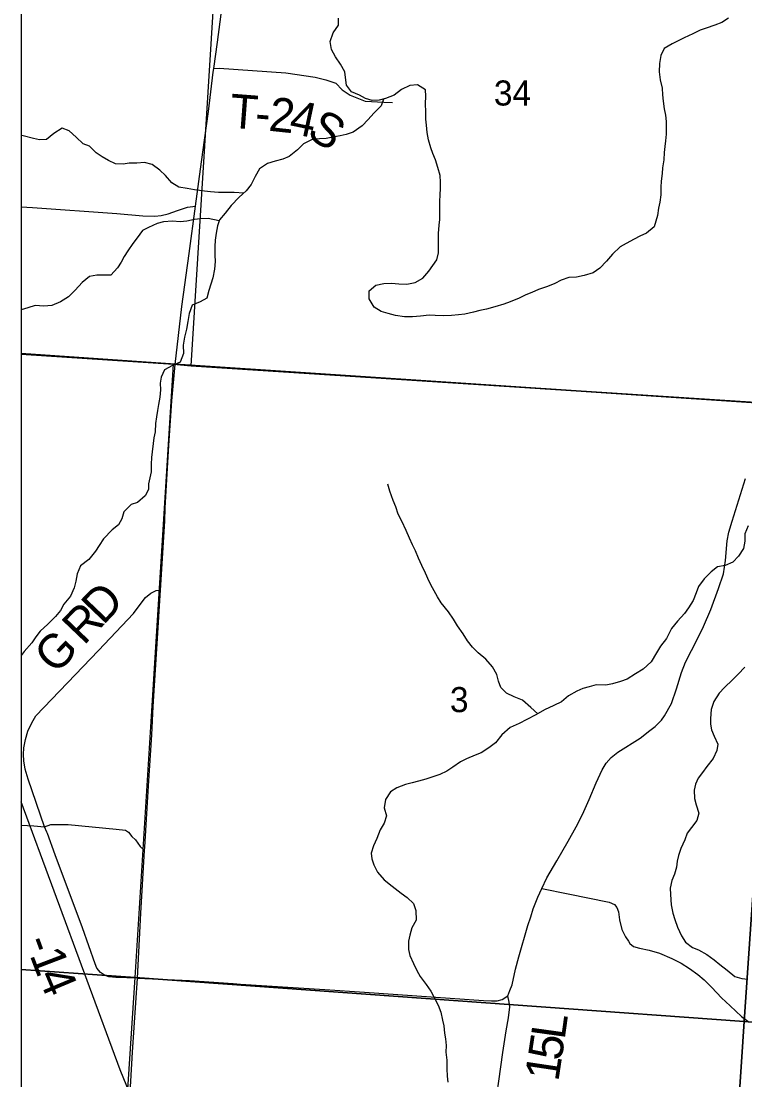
# Model space of a CAD drawing. Extents: x 0 to 34, y 0 to 22.
# Drawn here: x 2.1 to 3.309, y 17.985 to 19.753 of the extents above; entities that cross this region are included whole.
import ezdxf

# ---------------------------------------------------------------- set-up
doc = ezdxf.new("R2010")
doc.units = 0
for name, color, linetype in [('Default', 7, 'Continuous'), ('GM_X_County_Road', 7, 'Continuous'), ('GM_X_County_Road_Text', 7, 'Continuous'), ('GM_X_Minor_River', 7, 'Continuous'), ('GM_X_Rail_Line', 7, 'Continuous'), ('GM_X_Section', 7, 'Continuous'), ('GM_X_Section_Text', 7, 'Continuous'), ('GM_X_State_Route', 7, 'Continuous'), ('GM_X_Township_Road', 7, 'Continuous'), ('GM_X_Township_Road_Text', 7, 'Continuous'), ('SC_Scratch1', 7, 'Continuous'), ('SH_Data', 7, 'Continuous')]:
    doc.layers.add(name, color=color, linetype=linetype)

msp = doc.modelspace()

# ---------------------------------------------------------------- linework, layer by layer
at = {"layer": 'Default'}
for points in [[(2.1, 20.207), (2.1, 19.197), (2.3543, 19.1806), (2.3838, 19.1776), (2.446, 20.1823)], [(2.1, 19.197), (2.1, 18.1694), (2.2906, 18.1558), (2.3543, 19.1806)], [(2.1, 18.1694), (2.1, 17.1522), (2.2239, 17.1453), (2.2906, 18.1558)]]:
    msp.add_lwpolyline(points, close=True, dxfattribs=at)
at = {"layer": 'GM_X_County_Road'}
for points in [[(2.1431, 18.3985), (2.139, 18.4078), (2.1117, 18.4871), (2.1064, 18.504), (2.1043, 18.5178), (2.1037, 18.5286), (2.1043, 18.5396), (2.107, 18.5536), (2.1112, 18.5675), (2.1176, 18.5816), (2.1246, 18.5933), (2.1774, 18.6483), (2.2291, 18.702), (2.2874, 18.7638), (2.2969, 18.777), (2.3079, 18.791), (2.3166, 18.798), (2.3253, 18.8024), (2.3329, 18.8027)], [(2.2941, 18.1548), (2.2581, 18.1557), (2.2463, 18.1572), (2.2389, 18.1599), (2.2325, 18.1641), (2.2266, 18.1714), (2.2238, 18.1786), (2.2022, 18.2392), (2.1568, 18.361), (2.1439, 18.3966), (2.1431, 18.3985)]]:
    msp.add_lwpolyline(points, dxfattribs=at)
at = {"layer": 'GM_X_Minor_River'}
for points in [[(2.7752, 19.6154), (2.7756, 19.6283), (2.7752, 19.6385), (2.7619, 19.6472), (2.749, 19.646), (2.7354, 19.6395), (2.723, 19.63), (2.7086, 19.6243), (2.698, 19.6216), (2.6859, 19.6208), (2.6753, 19.6242), (2.665, 19.6299), (2.6518, 19.6352), (2.6434, 19.6465), (2.6415, 19.6594), (2.6407, 19.6689), (2.6335, 19.6818), (2.6247, 19.6939), (2.6182, 19.706), (2.6159, 19.7196), (2.6212, 19.7337), (2.6302, 19.7466), (2.6302, 19.7587)], [(3.2813, 19.7584), (3.2703, 19.7512), (3.2582, 19.747), (3.2439, 19.742), (3.234, 19.7382), (3.2215, 19.7325), (3.2072, 19.7256)], [(3.2072, 19.7256), (3.1974, 19.7203), (3.1872, 19.7157), (3.1739, 19.7077), (3.1683, 19.6959), (3.1661, 19.6827), (3.1654, 19.6686), (3.1673, 19.6554), (3.1704, 19.6417), (3.1711, 19.6304), (3.1723, 19.6198), (3.1739, 19.6069), (3.1758, 19.5963), (3.177, 19.586), (3.1774, 19.5762), (3.1774, 19.5648), (3.1763, 19.5538), (3.1748, 19.5439), (3.1737, 19.5341), (3.173, 19.5216), (3.1708, 19.5087), (3.1704, 19.4988), (3.169, 19.4863), (3.1682, 19.4761), (3.1683, 19.4632), (3.1668, 19.451), (3.1646, 19.4412), (3.1627, 19.4287), (3.1601, 19.4192), (3.1571, 19.4097), (3.1443, 19.3994), (3.1333, 19.3941), (3.1235, 19.3895), (3.1102, 19.3823), (3.1004, 19.3762), (3.0876, 19.3644), (3.0774, 19.3526), (3.0661, 19.3409), (3.0551, 19.3332), (3.04, 19.3287), (3.0272, 19.326), (3.0147, 19.3252), (3.0018, 19.3206), (2.9912, 19.3153), (2.9791, 19.3103), (2.964, 19.3054), (2.9527, 19.3004), (2.9428, 19.2962), (2.9315, 19.2909), (2.9164, 19.2848), (2.9058, 19.2809), (2.891, 19.2764), (2.877, 19.2722), (2.8657, 19.2699), (2.8555, 19.2676), (2.8411, 19.2641), (2.8305, 19.2629), (2.8184, 19.2618), (2.8055, 19.2614), (2.7915, 19.2617), (2.7813, 19.2624), (2.7669, 19.2609), (2.7533, 19.2597), (2.7404, 19.2597), (2.7249, 19.2616), (2.7128, 19.2649), (2.701, 19.2683), (2.6893, 19.2759), (2.6813, 19.2895), (2.6812, 19.3028), (2.6922, 19.3127), (2.7054, 19.315), (2.7187, 19.3157), (2.7308, 19.3146), (2.744, 19.3143), (2.7577, 19.317), (2.7705, 19.3242), (2.7807, 19.3356), (2.7875, 19.3455), (2.7939, 19.355), (2.7969, 19.3667), (2.7972, 19.3766), (2.7971, 19.3986), (2.7979, 19.4126), (2.799, 19.4221), (2.7993, 19.4411), (2.7992, 19.4528), (2.7996, 19.4627), (2.8003, 19.4744), (2.8003, 19.4847), (2.7995, 19.4956), (2.796, 19.5089), (2.7922, 19.5218), (2.7876, 19.5324), (2.7842, 19.5419), (2.7804, 19.5551), (2.778, 19.5672), (2.7769, 19.5797), (2.7757, 19.59), (2.7757, 19.6021), (2.7752, 19.6154)], [(2.7049, 19.6234), (2.7011, 19.6118), (2.689, 19.5996), (2.6796, 19.589), (2.6694, 19.5787), (2.6546, 19.5681), (2.6425, 19.5639), (2.6327, 19.562), (2.6202, 19.5597), (2.6096, 19.5577), (2.5983, 19.5566), (2.585, 19.5554), (2.5714, 19.5485), (2.5612, 19.5383), (2.5476, 19.5273), (2.5371, 19.5227), (2.5242, 19.5196), (2.5113, 19.5158), (2.4981, 19.507), (2.4906, 19.4941), (2.4842, 19.4808), (2.4755, 19.4698), (2.4638, 19.4592), (2.4506, 19.4455), (2.4408, 19.4326), (2.431, 19.4216), (2.428, 19.4113), (2.4258, 19.3992), (2.4239, 19.3878), (2.4236, 19.3772), (2.4236, 19.3624), (2.4237, 19.3522), (2.423, 19.3393), (2.42, 19.3249), (2.417, 19.3139), (2.4136, 19.3033), (2.4099, 19.2907), (2.3989, 19.2846), (2.3853, 19.2789), (2.3804, 19.2649), (2.3782, 19.2516), (2.376, 19.2391), (2.3726, 19.2254), (2.3707, 19.2122), (2.3712, 19.1985), (2.3655, 19.1841), (2.3527, 19.178), (2.3395, 19.1711), (2.3338, 19.159), (2.3323, 19.1488), (2.3324, 19.1374), (2.3317, 19.1256), (2.3294, 19.1131), (2.3276, 19.1033), (2.3261, 19.0926), (2.3246, 19.0813), (2.3235, 19.0676), (2.3217, 19.0574), (2.3202, 19.0479), (2.3187, 19.0342), (2.3176, 19.0248), (2.3173, 19.0134), (2.3169, 19.0005), (2.3147, 18.9906), (2.3128, 18.9804), (2.3129, 18.9709), (2.3072, 18.9603), (2.294, 18.9493), (2.2838, 18.9462), (2.2713, 18.9337), (2.2683, 18.9223), (2.2623, 18.912), (2.2517, 18.904), (2.2374, 18.8888), (2.2303, 18.8774), (2.2242, 18.8679), (2.2129, 18.8543), (2.1993, 18.8436), (2.1937, 18.8303), (2.1911, 18.8178), (2.1885, 18.8068), (2.1821, 18.7932), (2.1715, 18.7795), (2.1655, 18.7688), (2.1572, 18.759), (2.1447, 18.746), (2.1315, 18.7346), (2.1244, 18.7248), (2.118, 18.7149), (2.1048, 18.7008), (2.1, 18.6936)], [(2.4716, 19.4663), (2.4555, 19.4675), (2.4437, 19.4671), (2.4297, 19.4674), (2.4161, 19.4685), (2.4063, 19.4693), (2.3892, 19.4719), (2.3771, 19.4738), (2.3635, 19.476), (2.3517, 19.4836), (2.3411, 19.4957), (2.3316, 19.5047), (2.3187, 19.5142), (2.3062, 19.5172), (2.2929, 19.5164), (2.2804, 19.516), (2.2706, 19.5148), (2.2577, 19.5152), (2.246, 19.5208), (2.2354, 19.5269), (2.2251, 19.5337), (2.2141, 19.5446), (2.2035, 19.5488), (2.1921, 19.5597), (2.1803, 19.5703), (2.1682, 19.5745), (2.1546, 19.5657), (2.1421, 19.5558), (2.1304, 19.5554), (2.1206, 19.5573), (2.1031, 19.5618), (2.1, 19.5624)], [(2.4306, 19.42), (2.4125, 19.4238), (2.3992, 19.4234), (2.3894, 19.4219), (2.3765, 19.4192), (2.3655, 19.4184), (2.3527, 19.4191), (2.3375, 19.4183), (2.3269, 19.4153), (2.3126, 19.4088), (2.3028, 19.4038), (2.2937, 19.3917), (2.2865, 19.3822), (2.2779, 19.37), (2.2719, 19.3602), (2.267, 19.3507), (2.2609, 19.3412), (2.2496, 19.3294), (2.2261, 19.3293), (2.214, 19.3267), (2.2016, 19.3168), (2.1903, 19.3039), (2.1789, 19.2932), (2.1657, 19.2848), (2.151, 19.2787), (2.1381, 19.2772), (2.1233, 19.2783), (2.1112, 19.2745), (2.1, 19.2713)], [(2.9626, 18.5966), (2.9511, 18.607), (2.9371, 18.6194), (2.9234, 18.6247), (2.9105, 18.6311), (2.901, 18.6402), (2.8972, 18.6508), (2.8945, 18.6622), (2.8869, 18.6747), (2.8759, 18.6875), (2.8634, 18.6985), (2.8535, 18.708), (2.8455, 18.7182), (2.8383, 18.7303), (2.8288, 18.7435), (2.8219, 18.7545), (2.8136, 18.7666), (2.8014, 18.7818), (2.7953, 18.792), (2.7869, 18.8068), (2.7816, 18.8177), (2.7751, 18.8314), (2.769, 18.8439), (2.7633, 18.8564), (2.7583, 18.8685), (2.7534, 18.8787), (2.7484, 18.8901), (2.7431, 18.9026), (2.7359, 18.9181), (2.7298, 18.9302), (2.7256, 18.9423), (2.7214, 18.9526), (2.7156, 18.9681), (2.7122, 18.9802)], [(3.3139, 18.9104), (3.3083, 18.8971), (3.3083, 18.885), (3.3061, 18.8725), (3.2978, 18.8596), (3.2884, 18.8497), (3.2755, 18.8443), (3.263, 18.842), (3.2521, 18.8337), (3.2404, 18.8219), (3.231, 18.8093), (3.2272, 18.7983), (3.222, 18.7858), (3.2144, 18.7737), (3.208, 18.7638), (3.1959, 18.7512), (3.1861, 18.7391), (3.1775, 18.7224), (3.1677, 18.7095), (3.1609, 18.6981), (3.1523, 18.6833), (3.1387, 18.6711), (3.1262, 18.6631), (3.1122, 18.6544), (3.1009, 18.6505), (3.0873, 18.6467), (3.0763, 18.6444), (3.06, 18.6448), (3.0483, 18.6417), (3.0381, 18.6386), (3.0279, 18.6344), (3.0139, 18.6264), (3.0026, 18.6166), (2.9893, 18.6101), (2.9742, 18.6032), (2.9595, 18.5948), (2.9447, 18.5868), (2.9315, 18.58), (2.9164, 18.5735), (2.9028, 18.5613), (2.8919, 18.5477), (2.8809, 18.5397), (2.8681, 18.5313), (2.8582, 18.5271), (2.8435, 18.5214), (2.8337, 18.5164), (2.8208, 18.5073), (2.8106, 18.5005), (2.7989, 18.4951), (2.7876, 18.4909), (2.7759, 18.4871), (2.7638, 18.484), (2.7528, 18.4814), (2.7418, 18.4783)], [(3.3086, 18.6742), (3.2973, 18.6628), (3.2882, 18.6533), (3.2743, 18.6403), (3.2656, 18.6308), (3.2566, 18.6172), (3.2524, 18.6039), (3.251, 18.5887), (3.251, 18.5789), (3.2526, 18.5694), (3.2571, 18.5592), (3.2632, 18.5459), (3.2618, 18.5349), (3.2557, 18.522), (3.2452, 18.5087), (3.2376, 18.4985), (3.2305, 18.489), (3.226, 18.4787), (3.2237, 18.4688), (3.2245, 18.4552), (3.2272, 18.4442), (3.2318, 18.4302), (3.2281, 18.418), (3.2194, 18.4067), (3.2122, 18.3968), (3.2085, 18.3862), (3.2017, 18.3713), (3.1976, 18.36), (3.1957, 18.3501), (3.1946, 18.3402), (3.1909, 18.3285), (3.1864, 18.3178), (3.1838, 18.3053), (3.1842, 18.2947), (3.1854, 18.2773), (3.1884, 18.2633), (3.1915, 18.253), (3.1961, 18.2398), (3.2026, 18.2258), (3.2094, 18.2148), (3.2212, 18.2061), (3.2314, 18.2023), (3.2451, 18.1944), (3.2572, 18.1853), (3.2667, 18.1778), (3.2792, 18.1683), (3.2917, 18.1577), (3.3035, 18.1543), (3.3137, 18.1532)], [(2.7418, 18.4783), (2.7271, 18.4726), (2.7169, 18.4661), (2.7086, 18.4532), (2.7064, 18.4392), (2.7102, 18.4263), (2.7064, 18.4138), (2.6997, 18.4024), (2.6937, 18.3883), (2.6884, 18.3758), (2.6846, 18.3637), (2.6854, 18.3542), (2.6889, 18.3443), (2.6953, 18.3322), (2.7064, 18.319), (2.7197, 18.3084), (2.7345, 18.297), (2.7447, 18.2895), (2.7553, 18.2796), (2.7592, 18.2679), (2.7596, 18.252), (2.7524, 18.2387), (2.7491, 18.2265), (2.7468, 18.2167), (2.7469, 18.2027), (2.7492, 18.1928), (2.7553, 18.1792), (2.7606, 18.1678), (2.7663, 18.1576), (2.7762, 18.1443), (2.7842, 18.1334), (2.7895, 18.1227), (2.7964, 18.1095), (2.8006, 18.0978), (2.8037, 18.0849), (2.8056, 18.075), (2.8068, 18.0629), (2.8087, 18.0534), (2.8095, 18.0424), (2.8091, 18.0314), (2.8107, 18.0178), (2.8111, 18.0034), (2.8115, 17.9912), (2.8127, 17.9814)]]:
    msp.add_lwpolyline(points, dxfattribs=at)
at = {"layer": 'GM_X_Rail_Line'}
msp.add_lwpolyline([(2.1, 16.9893), (2.1704, 17.1051), (2.2013, 17.1731), (2.2243, 17.2382), (2.2428, 17.3133), (2.3248, 17.6437), (2.3306, 17.7087), (2.3319, 17.774), (2.3234, 17.8446), (2.3066, 17.9007), (2.2655, 18.002), (2.1, 18.4495)], dxfattribs=at)
at = {"layer": 'GM_X_Section'}
for points in [[(3.4572, 20.1141), (3.4007, 19.112), (3.378, 19.1131), (2.3838, 19.1776), (2.446, 20.1823)], [(2.3543, 19.1806), (2.3838, 19.1776), (3.378, 19.1131), (3.3075, 18.0826), (2.2906, 18.1558)], [(3.378, 19.1131), (3.4007, 19.112), (4.3808, 19.0475), (4.3187, 18.0057), (3.3075, 18.0826)], [(2.2906, 18.1558), (3.3075, 18.0826), (3.2396, 17.0555), (2.2239, 17.1453)], [(4.3187, 18.0057), (4.2561, 17.0047), (3.2396, 17.0555), (3.3075, 18.0826)]]:
    msp.add_lwpolyline(points, close=True, dxfattribs=at)
at = {"layer": 'GM_X_State_Route'}
for points in [[(2.3912, 19.4446), (2.3997, 19.506), (2.4063, 19.5548), (2.4127, 19.6028), (2.4207, 19.6683), (2.4216, 19.6746), (2.4278, 19.7185), (2.4366, 19.7864), (2.4499, 19.8758), (2.465, 19.9651), (2.5191, 20.2008), (2.5499, 20.3338), (2.5565, 20.3632)], [(2.2941, 18.1548), (2.3, 18.2633), (2.3062, 18.3682), (2.3066, 18.3739), (2.3128, 18.4761), (2.3181, 18.5614), (2.3206, 18.6084), (2.3281, 18.7311), (2.3301, 18.7586), (2.3329, 18.8027), (2.3397, 18.9183), (2.3406, 18.9404), (2.3468, 19.0449), (2.3516, 19.119), (2.3574, 19.1799), (2.3685, 19.2767), (2.3808, 19.3652), (2.3912, 19.4446)], [(2.454, 18.1459), (2.466, 18.1451), (2.6069, 18.1357), (2.6735, 18.1313), (2.872, 18.1173), (2.8854, 18.1169), (2.8949, 18.1169), (2.9032, 18.1194), (2.9125, 18.1254), (2.9163, 18.1343), (2.9199, 18.1438), (2.9258, 18.17), (2.9311, 18.1903), (2.9462, 18.2429), (2.9509, 18.2573), (2.9549, 18.2704), (2.9627, 18.2903), (2.9697, 18.3048), (2.978, 18.3222), (2.9948, 18.351), (3.0136, 18.3835), (3.0271, 18.4077), (3.0372, 18.4281), (3.0486, 18.4531), (3.0602, 18.4813), (3.0702, 18.5027), (3.0768, 18.5138), (3.0853, 18.5237), (3.0963, 18.5321), (3.1335, 18.5557), (3.1501, 18.5687), (3.159, 18.5754), (3.1692, 18.5858), (3.1744, 18.5932), (3.1858, 18.6135), (3.1946, 18.6382), (3.2028, 18.6652), (3.2097, 18.6825), (3.2292, 18.7218), (3.2396, 18.7421), (3.2519, 18.7708), (3.2647, 18.8059), (3.2727, 18.83), (3.2763, 18.8523), (3.2791, 18.8853), (3.282, 18.8999), (3.2872, 18.9182), (3.3095, 18.9897)], [(2.168, 17.1208), (2.176, 17.1355), (2.1997, 17.1916), (2.2065, 17.2125), (2.217, 17.2467), (2.2264, 17.2823), (2.2362, 17.3366), (2.2477, 17.4176), (2.2517, 17.4591), (2.2555, 17.5254), (2.2633, 17.6513), (2.2706, 17.7708), (2.2779, 17.8962), (2.2804, 17.9343), (2.2859, 18.031), (2.2941, 18.1548)], [(2.2941, 18.1548), (2.3813, 18.151), (2.454, 18.1459)]]:
    msp.add_lwpolyline(points, dxfattribs=at)
at = {"layer": 'GM_X_Township_Road'}
for points in [[(2.4216, 19.6746), (2.4308, 19.6749), (2.5419, 19.6673), (2.5911, 19.6601), (2.6087, 19.6555), (2.6253, 19.6497), (2.636, 19.6388), (2.6493, 19.63), (2.6747, 19.6197), (2.7058, 19.6184), (2.7203, 19.6175)], [(2.1, 19.4434), (2.1189, 19.4422), (2.2595, 19.4324), (2.3033, 19.4281), (2.3232, 19.4278), (2.3338, 19.429), (2.3453, 19.4317), (2.361, 19.4374), (2.3778, 19.443), (2.3912, 19.4446)], [(2.1, 18.4106), (2.121, 18.4091), (2.139, 18.4078)], [(2.139, 18.4078), (2.1494, 18.4116), (2.1783, 18.4114), (2.2588, 18.4036), (2.2742, 18.4023), (2.2793, 18.3985), (2.285, 18.3917), (2.291, 18.3862), (2.2988, 18.375), (2.3062, 18.3682)], [(2.9697, 18.3048), (3.0134, 18.2956), (3.0818, 18.2819), (3.091, 18.2778), (3.0948, 18.2731), (3.0974, 18.2658), (3.0991, 18.2522), (3.1029, 18.2364), (3.1095, 18.2241), (3.1141, 18.2167)], [(3.1141, 18.2167), (3.1164, 18.213), (3.1226, 18.208), (3.1325, 18.2051), (3.1489, 18.2018), (3.1661, 18.1964), (3.1865, 18.1878), (3.2022, 18.1798), (3.2163, 18.1712), (3.2298, 18.1611), (3.2408, 18.1518), (3.2535, 18.1392), (3.2694, 18.1219), (3.2839, 18.1089), (3.303, 18.0907), (3.3159, 18.0812)], [(2.8886, 17.9063), (2.8922, 17.9448), (2.8977, 17.9828), (2.9042, 18.0306), (2.9097, 18.0671), (2.9136, 18.0887), (2.9161, 18.1067), (2.915, 18.115), (2.9125, 18.1254)]]:
    msp.add_lwpolyline(points, dxfattribs=at)
at = {"layer": 'SC_Scratch1'}
for points in [[(5.53, 20.9), (2.1, 20.9), (2.1, 19.1982), (2.3572, 19.1804), (3.3448, 19.1146), (4.3628, 19.0495), (4.7394, 19.0241), (4.7997, 19.0196), (5.182, 18.9932), (5.4007, 18.9779), (5.4089, 19.0989), (5.4469, 19.6641), (5.4955, 20.3864)], [(2.1, 19.1982), (2.1, 14.1), (5.0535, 14.1), (5.0814, 14.5016), (5.1049, 14.8414), (5.1794, 15.9156), (5.2761, 17.2534), (5.2869, 17.4026), (5.3506, 18.2846), (5.3662, 18.4999), (5.4007, 18.9779), (5.182, 18.9932), (4.7997, 19.0196), (4.7394, 19.0241), (4.3628, 19.0495), (3.3448, 19.1146), (2.3572, 19.1804)]]:
    msp.add_lwpolyline(points, close=True, dxfattribs=at)
at = {"layer": 'SH_Data'}
msp.add_line((2.1, 20.9), (2.1, 14.1), dxfattribs=at)

# ---------------------------------------------------------------- texts
at = {"layer": 'GM_X_County_Road_Text'}
for s, rotation, p in [('D', 46.3054, (2.2367, 18.7433)), ('R', 46.3059, (2.2045, 18.7095)), ('G', 46.3035, (2.1578, 18.6607)), ('-', 290.335, (2.1054, 18.2161)), ('1', 290.8712, (2.1137, 18.1937)), ('4', 292.7486, (2.1269, 18.1591))]:
    msp.add_text(s, height=0.0568, rotation=rotation, dxfattribs=at).set_placement(p)
at = {"layer": 'GM_X_Section_Text'}
for s, height, p in [('34', 0.04186, (2.8894, 19.6125)), ('3', 0.0419, (2.816, 18.5992))]:
    msp.add_text(s, height=height, rotation=0, dxfattribs=at).set_placement(p)
at = {"layer": 'GM_X_Township_Road_Text'}
for s, rotation, p in [('T', 355.6115, (2.4469, 19.5757)), ('2', 353.8736, (2.512, 19.5706)), ('4', 347.9736, (2.5453, 19.5671)), ('-', 355.3271, (2.4892, 19.5724)), ('S', 327.4618, (2.5746, 19.5618)), ('L', 82.1031, (3.0075, 18.0509)), ('5', 81.4718, (3.0022, 18.0156)), ('1', 81.4651, (2.997, 17.981))]:
    msp.add_text(s, height=0.0568, rotation=rotation, dxfattribs=at).set_placement(p)

doc.saveas('drawing.dxf')
